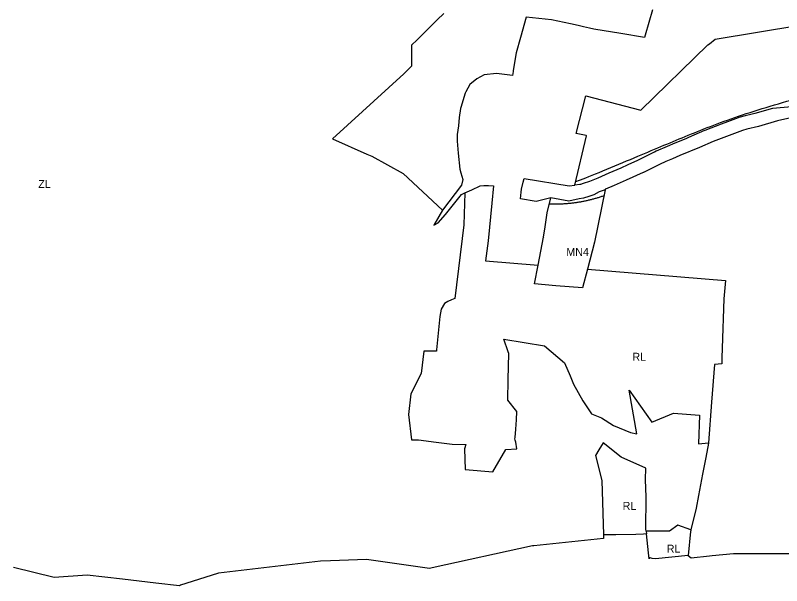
# Model space of a CAD drawing. Extents: x 7413438 to 7416393, y 5541665 to 5544118.
# Drawn here: x 7414051 to 7414626, y 5541665 to 5542093 of the extents above; entities that cross this region are included whole.
import ezdxf

# ---------------------------------------------------------------- set-up
doc = ezdxf.new("R2010")
doc.units = 0
for name, color, linetype in [('linie_rozgraniczajace', 7, 'Continuous'), ('linie_zabudowy_nieprzekraczalne', 7, 'Continuous'), ('oznaczenia_przeznaczen', 7, 'Continuous')]:
    doc.layers.add(name, color=color, linetype=linetype)

msp = doc.modelspace()

# ---------------------------------------------------------------- linework, layer by layer
at = {"layer": 'linie_rozgraniczajace'}
for p, q in [((7414529.01, 5542097.02), (7414523.67, 5542078.12)), ((7414367.68, 5542089.51), (7414362.88, 5542084.79)), ((7414372.56, 5542094.31), (7414367.68, 5542089.51)), ((7414434.49, 5542091.61), (7414430.08, 5542076.34)), ((7414453.3, 5542089.68), (7414434.49, 5542091.61)), ((7414467.62, 5542086.55), (7414453.3, 5542089.68)), ((7414362.88, 5542084.79), (7414359.3, 5542081.27)), ((7414473.35, 5542085.25), (7414467.62, 5542086.55)), ((7414477.33, 5542084.35), (7414473.35, 5542085.25)), ((7414481.85, 5542083.31), (7414477.33, 5542084.35)), ((7414485.15, 5542082.68), (7414481.85, 5542083.31)), ((7414576.01, 5542075.09), (7414650.75, 5542087.45)), ((7414357.2, 5542079.2), (7414352.57, 5542074.65)), ((7414359.3, 5542081.27), (7414357.2, 5542079.2)), ((7414505.25, 5542079.39), (7414485.15, 5542082.68)), ((7414523.19, 5542076.44), (7414505.25, 5542079.39)), ((7414523.67, 5542078.12), (7414523.19, 5542076.44)), ((7414352.57, 5542074.65), (7414348.53, 5542070.68)), ((7414430.08, 5542076.34), (7414426.77, 5542064.83)), ((7414570.47, 5542070.74), (7414571.71, 5542071.67)), ((7414571.71, 5542071.67), (7414576.01, 5542075.09)), ((7414348.51, 5542067.3), (7414348.46, 5542060.68)), ((7414348.53, 5542070.68), (7414348.51, 5542067.3)), ((7414520.43, 5542021.94), (7414570.47, 5542070.74)), ((7414348.46, 5542060.68), (7414348.43, 5542054.82)), ((7414426.77, 5542064.83), (7414424.65, 5542051.58)), ((7414348.25, 5542054.64), (7414342.72, 5542049.09)), ((7414348.26, 5542054.64), (7414348.25, 5542054.64)), ((7414348.43, 5542054.82), (7414348.26, 5542054.64)), ((7414342.72, 5542049.09), (7414289.25, 5542000.3)), ((7414402.94, 5542048.39), (7414397.35, 5542045.4)), ((7414412.05, 5542049.47), (7414402.94, 5542048.39)), ((7414424.07, 5542047.94), (7414412.05, 5542049.47)), ((7414424.53, 5542050.83), (7414424.07, 5542047.94)), ((7414424.65, 5542051.58), (7414424.53, 5542050.83)), ((7414397.35, 5542045.4), (7414392.2, 5542041.17)), ((7414392.2, 5542041.17), (7414389.14, 5542035.58)), ((7414388.57, 5542034.53), (7414386.89, 5542028.85)), ((7414389.14, 5542035.58), (7414388.57, 5542034.53)), ((7414471.89, 5542004.48), (7414479.23, 5542032.71)), ((7414479.23, 5542032.71), (7414520.43, 5542021.94)), ((7414386.89, 5542028.85), (7414385.61, 5542024.55)), ((7414385.17, 5542023.05), (7414384.08, 5542016.34)), ((7414385.61, 5542024.55), (7414385.17, 5542023.05)), ((7414618.97, 5542023.08), (7414605.92, 5542019.4)), ((7414639.37, 5542024.87), (7414618.97, 5542023.08)), ((7414384.08, 5542016.34), (7414383.55, 5542010.08)), ((7414593.27, 5542016.15), (7414585.34, 5542013.11)), ((7414593.57, 5542016.25), (7414593.27, 5542016.15)), ((7414593.83, 5542016.32), (7414593.57, 5542016.25)), ((7414598.59, 5542017.54), (7414593.83, 5542016.32)), ((7414602.83, 5542018.61), (7414598.59, 5542017.54)), ((7414605.92, 5542019.4), (7414602.83, 5542018.61)), ((7414644.1, 5542018.75), (7414622.76, 5542013.76)), ((7414383.55, 5542010.08), (7414382.6, 5542003.71)), ((7414580.62, 5542011.3), (7414568.26, 5542006.62)), ((7414585.34, 5542013.11), (7414580.62, 5542011.3)), ((7414608.45, 5542009.73), (7414599.88, 5542007.55)), ((7414622.76, 5542013.76), (7414608.45, 5542009.73)), ((7414382.6, 5542003.71), (7414382.62, 5541998.54)), ((7414470.84, 5541965.62), (7414479.7, 5542002.66)), ((7414479.26, 5542002.77), (7414471.89, 5542004.48)), ((7414479.71, 5542002.66), (7414479.26, 5542002.77)), ((7414479.7, 5542002.66), (7414479.71, 5542002.66)), ((7414568.01, 5542006.52), (7414556.17, 5542001.3)), ((7414568.23, 5542006.61), (7414568.01, 5542006.52)), ((7414568.26, 5542006.62), (7414568.23, 5542006.61)), ((7414596.58, 5542006.7), (7414574.59, 5541998.32)), ((7414599.88, 5542007.55), (7414596.58, 5542006.7)), ((7414289.25, 5542000.3), (7414314.9, 5541988.97)), ((7414382.62, 5541998.54), (7414383.36, 5541989.73)), ((7414545.76, 5541997.11), (7414540.01, 5541994.63)), ((7414545.87, 5541997.15), (7414545.76, 5541997.11)), ((7414554.07, 5542000.45), (7414545.87, 5541997.15)), ((7414556.17, 5542001.3), (7414554.07, 5542000.45)), ((7414574.59, 5541998.32), (7414564.33, 5541993.97)), ((7414531.88, 5541991.05), (7414530.6, 5541990.48)), ((7414539.97, 5541994.62), (7414531.88, 5541991.05)), ((7414540.01, 5541994.63), (7414539.97, 5541994.62)), ((7414564.33, 5541993.97), (7414549.66, 5541987.9)), ((7414314.9, 5541988.97), (7414318.58, 5541987.37)), ((7414318.58, 5541987.37), (7414342.19, 5541974.3)), ((7414383.36, 5541989.73), (7414384.69, 5541977.63)), ((7414530.39, 5541990.38), (7414517.87, 5541984.13)), ((7414530.52, 5541990.44), (7414530.39, 5541990.38)), ((7414530.6, 5541990.48), (7414530.52, 5541990.44)), ((7414543.98, 5541985.46), (7414539.12, 5541983.31)), ((7414549.66, 5541987.9), (7414543.98, 5541985.46)), ((7414510.72, 5541980.9), (7414505.4, 5541978.49)), ((7414517.87, 5541984.13), (7414510.72, 5541980.9)), ((7414534.75, 5541981.38), (7414522.25, 5541975.14)), ((7414538.53, 5541983.05), (7414534.75, 5541981.38)), ((7414539.12, 5541983.31), (7414538.53, 5541983.05)), ((7414342.19, 5541974.3), (7414371.76, 5541946.85)), ((7414384.69, 5541977.63), (7414385.42, 5541974.86)), ((7414385.42, 5541974.86), (7414386.92, 5541969.81)), ((7414496.31, 5541974.65), (7414487.98, 5541971.01)), ((7414496.37, 5541974.68), (7414496.31, 5541974.65)), ((7414505.4, 5541978.49), (7414496.37, 5541974.68)), ((7414522.08, 5541975.06), (7414509.46, 5541969.35)), ((7414522.12, 5541975.08), (7414522.08, 5541975.06)), ((7414522.25, 5541975.14), (7414522.12, 5541975.08)), ((7414386.92, 5541969.81), (7414385.91, 5541965.64)), ((7414430.96, 5541962.57), (7414432.22, 5541967.95)), ((7414432.22, 5541967.95), (7414432.85, 5541970.71)), ((7414432.85, 5541970.71), (7414466.62, 5541965.06)), ((7414481.77, 5541968.42), (7414477.11, 5541966.85)), ((7414487.98, 5541971.01), (7414481.77, 5541968.42)), ((7414509.34, 5541969.3), (7414500.28, 5541965.48)), ((7414509.46, 5541969.35), (7414509.34, 5541969.3)), ((7414385.91, 5541965.64), (7414371.76, 5541946.85)), ((7414393.65, 5541962.1), (7414399.82, 5541965.08)), ((7414399.82, 5541965.08), (7414402.73, 5541965.52)), ((7414402.73, 5541965.52), (7414406.24, 5541965.52)), ((7414406.24, 5541965.52), (7414409.97, 5541965.21)), ((7414409.97, 5541965.21), (7414408.69, 5541952.17)), ((7414430.69, 5541960.28), (7414430.96, 5541962.57)), ((7414466.62, 5541965.06), (7414470.84, 5541965.62)), ((7414474.65, 5541966.13), (7414470.84, 5541965.62)), ((7414475.13, 5541966.2), (7414474.65, 5541966.13)), ((7414477.11, 5541966.85), (7414475.13, 5541966.2)), ((7414493.68, 5541962.59), (7414493.6, 5541962.16)), ((7414493.78, 5541962.63), (7414493.68, 5541962.59)), ((7414500.28, 5541965.48), (7414493.78, 5541962.63)), ((7414373.92, 5541943.75), (7414385.87, 5541958.71)), ((7414385.87, 5541958.71), (7414388.43, 5541959.92)), ((7414388.43, 5541959.92), (7414387.52, 5541936.03)), ((7414388.43, 5541959.92), (7414393.65, 5541962.1)), ((7414430.12, 5541955.31), (7414430.69, 5541960.28)), ((7414481.46, 5541957.1), (7414477.31, 5541955.93)), ((7414485.03, 5541958.53), (7414481.46, 5541957.1)), ((7414489.01, 5541960.62), (7414485.03, 5541958.53)), ((7414493.56, 5541962.14), (7414485.67, 5541923.01)), ((7414493.56, 5541962.14), (7414489.01, 5541960.62)), ((7414493.6, 5541962.16), (7414493.56, 5541962.14)), ((7414408.69, 5541952.17), (7414405.88, 5541923.92)), ((7414441.97, 5541953.42), (7414430.12, 5541955.31)), ((7414452.77, 5541956.23), (7414441.97, 5541953.42)), ((7414450.22, 5541944.91), (7414452.77, 5541956.23)), ((7414466.41, 5541953.73), (7414452.77, 5541956.23)), ((7414474.19, 5541955.32), (7414466.41, 5541953.73)), ((7414477.31, 5541955.93), (7414474.19, 5541955.32)), ((7414371.76, 5541946.85), (7414365.25, 5541935.68)), ((7414368.42, 5541937.42), (7414373.92, 5541943.75)), ((7414448.35, 5541932.79), (7414450.22, 5541944.91)), ((7414365.25, 5541935.68), (7414368.42, 5541937.42)), ((7414387.52, 5541936.03), (7414380.78, 5541880.71)), ((7414447.43, 5541926.9), (7414448.35, 5541932.79)), ((7414405.88, 5541923.92), (7414403.78, 5541908.96)), ((7414443.34, 5541905.7), (7414447.4, 5541926.63)), ((7414447.4, 5541926.63), (7414447.68, 5541926.87)), ((7414447.68, 5541926.87), (7414447.43, 5541926.9)), ((7414485.67, 5541923.01), (7414480.27, 5541902.65)), ((7414403.78, 5541908.96), (7414443.34, 5541905.7)), ((7414440.61, 5541891.65), (7414443.34, 5541905.7)), ((7414480.27, 5541902.65), (7414476.55, 5541888.58)), ((7414480.27, 5541902.65), (7414583.76, 5541894.13)), ((7414583.76, 5541894.13), (7414582.45, 5541880.39)), ((7414456.69, 5541890.1), (7414440.61, 5541891.65)), ((7414476.55, 5541888.58), (7414456.69, 5541890.1)), ((7414373.25, 5541876.9), (7414370.65, 5541872.73)), ((7414375.6, 5541878.4), (7414373.25, 5541876.9)), ((7414378.33, 5541879.62), (7414375.6, 5541878.4)), ((7414380.78, 5541880.71), (7414378.33, 5541879.62)), ((7414582.45, 5541880.39), (7414581.31, 5541843.47)), ((7414370.65, 5541872.73), (7414369.57, 5541867.16)), ((7414369.57, 5541867.16), (7414368.62, 5541857.17)), ((7414368.62, 5541857.17), (7414367.18, 5541842.25)), ((7414420.84, 5541840.8), (7414417.75, 5541850.32)), ((7414417.75, 5541850.32), (7414448.02, 5541845.32)), ((7414367.18, 5541842.25), (7414367.09, 5541841.29)), ((7414448.02, 5541845.32), (7414463.19, 5541832.4)), ((7414581.31, 5541843.47), (7414581.17, 5541836.2)), ((7414357.54, 5541841.15), (7414355.67, 5541824.44)), ((7414367.09, 5541841.29), (7414357.54, 5541841.15)), ((7414421.28, 5541839.43), (7414420.84, 5541840.8)), ((7414420.95, 5541819.94), (7414421.28, 5541839.43)), ((7414581.17, 5541836.2), (7414581.09, 5541831.82)), ((7414463.19, 5541832.4), (7414467.3, 5541822.61)), ((7414575.65, 5541831.34), (7414573.41, 5541802.89)), ((7414581.09, 5541831.82), (7414575.65, 5541831.34)), ((7414355.67, 5541824.44), (7414347.87, 5541809.21)), ((7414420.69, 5541804.48), (7414420.95, 5541819.94)), ((7414467.3, 5541822.61), (7414469.91, 5541816.39)), ((7414469.91, 5541816.39), (7414476.74, 5541804.01)), ((7414347.87, 5541809.21), (7414346.21, 5541793.86)), ((7414517.35, 5541779.27), (7414511.69, 5541811.94)), ((7414511.69, 5541811.94), (7414528.65, 5541788.04)), ((7414427.46, 5541795.97), (7414420.69, 5541804.48)), ((7414476.74, 5541804.01), (7414483.33, 5541794.37)), ((7414573.41, 5541802.89), (7414571.06, 5541772.49)), ((7414427.02, 5541789.86), (7414427.46, 5541795.97)), ((7414346.21, 5541793.86), (7414348.42, 5541774.72)), ((7414426.51, 5541782.77), (7414427.02, 5541789.86)), ((7414483.33, 5541794.37), (7414490.78, 5541791.24)), ((7414490.78, 5541791.24), (7414499.9, 5541785.41)), ((7414528.65, 5541788.04), (7414544.9, 5541794.63)), ((7414544.9, 5541794.63), (7414564.36, 5541793.25)), ((7414564.36, 5541793.25), (7414563.67, 5541771.74)), ((7414499.9, 5541785.41), (7414512.58, 5541780.25)), ((7414426.06, 5541776.52), (7414426.51, 5541782.77)), ((7414512.58, 5541780.25), (7414517.35, 5541779.27)), ((7414348.42, 5541774.72), (7414353.72, 5541774.75)), ((7414353.72, 5541774.75), (7414366.98, 5541773.02)), ((7414366.98, 5541773.02), (7414379.01, 5541771.62)), ((7414425.99, 5541775.53), (7414426.06, 5541776.51)), ((7414426.19, 5541774.61), (7414425.99, 5541775.53)), ((7414426.06, 5541776.51), (7414426.06, 5541776.52)), ((7414426.54, 5541773.07), (7414426.19, 5541774.61)), ((7414427.41, 5541768.08), (7414426.54, 5541773.07)), ((7414379.01, 5541771.62), (7414389.09, 5541771.36)), ((7414389.09, 5541771.36), (7414388.12, 5541768.04)), ((7414388.12, 5541768.04), (7414388.61, 5541752.47)), ((7414409.31, 5541750.8), (7414419.18, 5541767.59)), ((7414419.18, 5541767.59), (7414427.41, 5541768.08)), ((7414488.94, 5541767.14), (7414486.41, 5541763)), ((7414492.16, 5541772.4), (7414488.94, 5541767.14)), ((7414505.71, 5541761.64), (7414492.16, 5541772.4)), ((7414563.67, 5541771.74), (7414571.06, 5541772.49)), ((7414571.04, 5541772.38), (7414568.97, 5541761.42)), ((7414571.06, 5541772.49), (7414571.04, 5541772.38)), ((7414486.41, 5541763), (7414491.05, 5541744.27)), ((7414524.1, 5541753.54), (7414505.71, 5541761.64)), ((7414568.97, 5541761.42), (7414566.52, 5541749.11)), ((7414388.61, 5541752.47), (7414409.31, 5541750.8)), ((7414523.84, 5541745.04), (7414524.1, 5541753.54)), ((7414491.05, 5541744.27), (7414492.37, 5541703.62)), ((7414524.35, 5541731.79), (7414523.84, 5541745.04)), ((7414566.52, 5541749.11), (7414563.59, 5541733.06)), ((7414563.59, 5541733.06), (7414561.91, 5541723.46)), ((7414524.03, 5541707.76), (7414524.35, 5541731.79)), ((7414561.91, 5541723.46), (7414557.95, 5541707.26)), ((7414548.02, 5541710.7), (7414541.84, 5541706.39)), ((7414557.95, 5541707.26), (7414548.02, 5541710.7)), ((7414516.6, 5541703.67), (7414501.67, 5541703.44)), ((7414522.23, 5541704.08), (7414516.6, 5541703.67)), ((7414524.59, 5541704.26), (7414522.23, 5541704.08)), ((7414524.26, 5541706.3), (7414524.03, 5541707.76)), ((7414541.07, 5541706.38), (7414524.26, 5541706.3)), ((7414524.26, 5541706.3), (7414524.59, 5541704.26)), ((7414526.17, 5541690.15), (7414524.59, 5541704.26)), ((7414541.84, 5541706.39), (7414541.07, 5541706.38)), ((7414557.62, 5541705.94), (7414555.82, 5541688.12)), ((7414557.86, 5541706.89), (7414557.62, 5541705.94)), ((7414557.95, 5541707.26), (7414557.86, 5541706.89)), ((7414492.41, 5541700.69), (7414440.17, 5541695.35)), ((7414501.67, 5541703.44), (7414492.37, 5541703.62)), ((7414492.37, 5541703.62), (7414492.41, 5541700.69)), ((7414439.03, 5541695.24), (7414363.87, 5541678.76)), ((7414440.17, 5541695.35), (7414439.03, 5541695.24)), ((7414526.67, 5541685.67), (7414526.17, 5541690.15)), ((7414526.69, 5541686.43), (7414526.67, 5541685.67)), ((7414528.95, 5541685.76), (7414526.69, 5541686.43)), ((7414555.82, 5541688.12), (7414531.26, 5541685.58)), ((7414555.71, 5541687.77), (7414555.82, 5541688.12)), ((7414558.06, 5541686.16), (7414555.71, 5541687.77)), ((7414571.82, 5541687.48), (7414558.06, 5541686.16)), ((7414573.9, 5541687.73), (7414571.82, 5541687.48)), ((7414589.86, 5541689.34), (7414573.9, 5541687.73)), ((7414615.09, 5541689.28), (7414589.86, 5541689.34)), ((7414625.3, 5541689.3), (7414615.09, 5541689.28)), ((7414638.16, 5541689.25), (7414625.3, 5541689.3)), ((7414280.19, 5541683.86), (7414203.8, 5541674.82)), ((7414287.74, 5541684.15), (7414280.19, 5541683.86)), ((7414314.69, 5541685.16), (7414287.74, 5541684.15)), ((7414361.91, 5541678.34), (7414314.69, 5541685.16)), ((7414531.26, 5541685.58), (7414528.95, 5541685.76)), ((7414080.62, 5541671.45), (7414049.96, 5541679.14)), ((7414363.87, 5541678.76), (7414361.91, 5541678.34)), ((7414105.19, 5541673.23), (7414080.62, 5541671.45)), ((7414131.83, 5541670.3), (7414105.19, 5541673.23)), ((7414156.72, 5541667.4), (7414131.83, 5541670.3)), ((7414203.01, 5541674.54), (7414175.3, 5541665.71)), ((7414203.8, 5541674.82), (7414203.01, 5541674.54)), ((7414174.52, 5541665.44), (7414156.72, 5541667.4)), ((7414175.3, 5541665.71), (7414174.52, 5541665.44))]:
    msp.add_line(p, q, dxfattribs=at)
at = {"layer": 'linie_zabudowy_nieprzekraczalne'}
for points, degree in [([(7414471.48, 5541968.46), (7414475.51, 5541969.6), (7414513.16, 5541985.19), (7414548.82, 5542000.27), (7414585.9, 5542015.38), (7414619.44, 5542025.72), (7414635.92, 5542030.24)], 3), ([(7414492.62, 5541957.67), (7414473.19, 5541950.78), (7414451.63, 5541951.34)], 2)]:
    msp.add_open_spline(points, degree=degree, dxfattribs=at)

# ---------------------------------------------------------------- texts
at = {"layer": 'oznaczenia_przeznaczen'}
for s, p in [('ZL', (7414068.57, 5541963.56)), ('MN4', (7414464.46, 5541912.62)), ('RL', (7414514, 5541833.99)), ('RL', (7414506.69, 5541722.27)), ('RL', (7414539.78, 5541690.15))]:
    msp.add_text(s, height=6, dxfattribs=at).set_placement(p)

doc.saveas('drawing.dxf')
